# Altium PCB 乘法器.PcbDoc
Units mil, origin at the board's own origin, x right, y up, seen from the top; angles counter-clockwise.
Board outline 6000 x 4000 mil, 2 copper layers (Top Layer, Bottom Layer); 16 components, 10 nets, 49 pads, 0 vias.
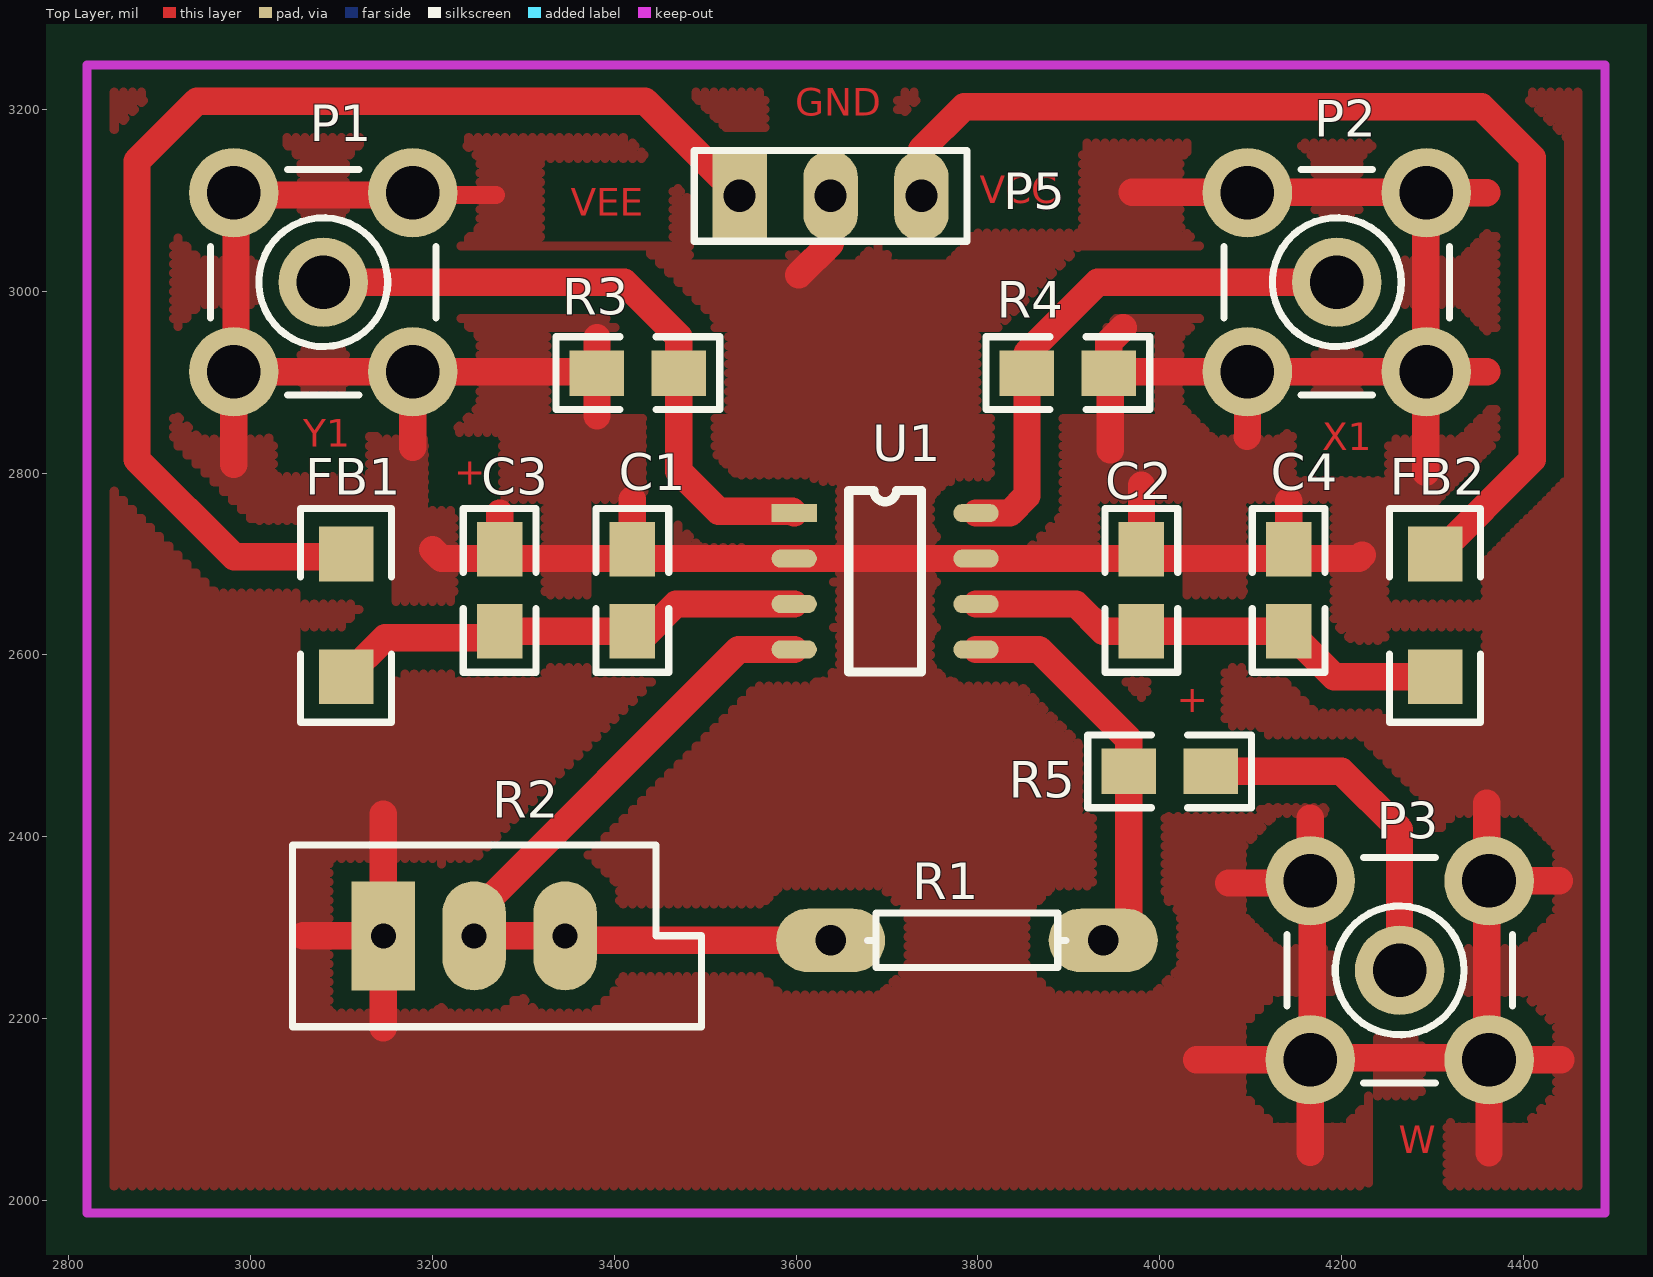
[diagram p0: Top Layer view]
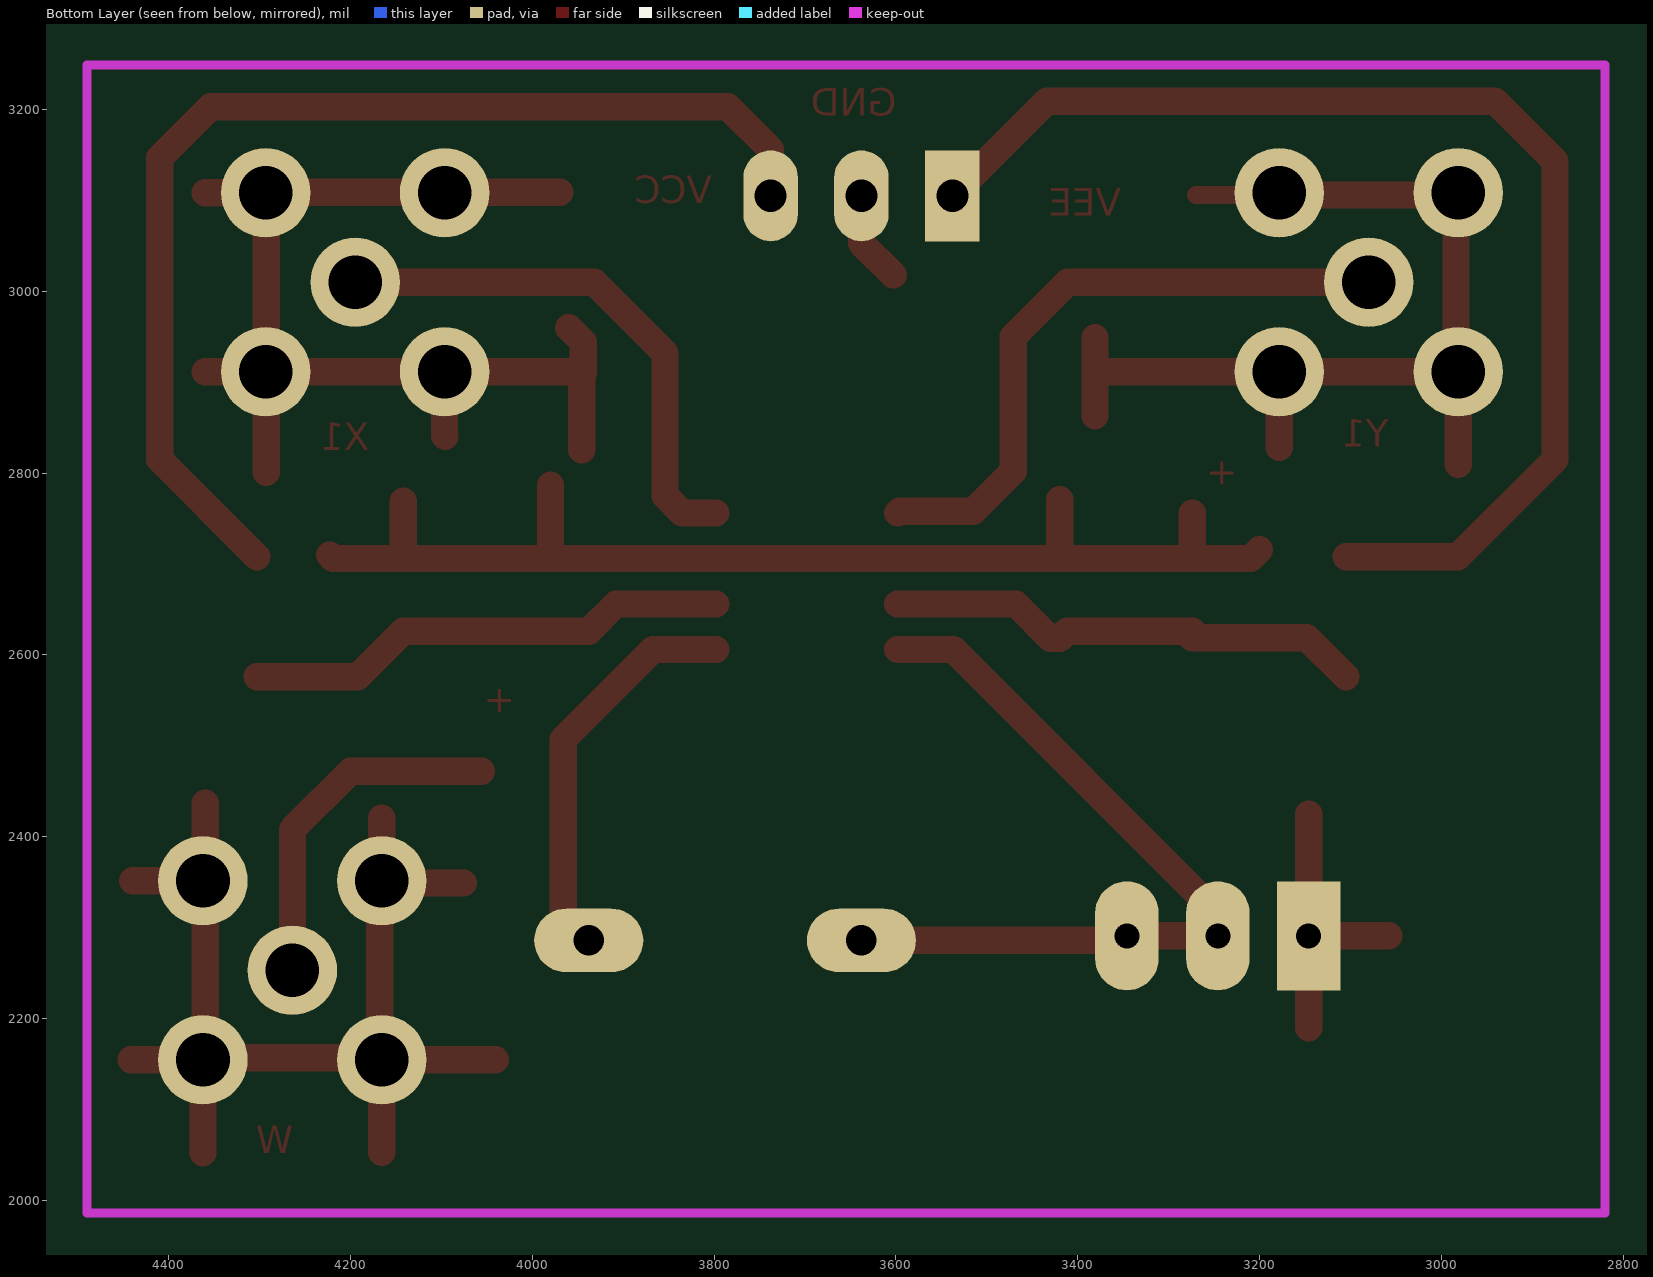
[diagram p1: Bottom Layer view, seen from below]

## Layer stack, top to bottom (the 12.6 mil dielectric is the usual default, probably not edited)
Top Layer: signal copper 1.4
Dielectric: dielectric 12.6, FR-4, Dk 4.8
Bottom Layer: signal copper 1.4

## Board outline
1000,1000 7000,1000 7000,5000 1000,5000

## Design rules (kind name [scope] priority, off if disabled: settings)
Clearance [All] p1: gap=20
PolygonConnect [All] p1: connectstyle=Relief reliefconductorwidth=10 reliefentries=4 polygonreliefangle="90 Angle"
RoutingVias [All] p1: holewidth=28 width=50 viastyle="Through Hole" minholewidth=28 minwidth=50 maxholewidth=28 maxwidth=50
SilkscreenOverComponentPads [All] p1: minsilkscreentomaskgap=10
SolderMaskExpansion [All] p1: expansion=4
Width [All] p1: maxlimit=50 minlimit=20 preferedwidth=30
27 further rules are at their usual default settings.

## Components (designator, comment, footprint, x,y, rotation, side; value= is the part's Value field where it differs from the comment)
C1 "Cap Pol3" 0805 3420,2716 r270 top
C2 "Cap Pol3" 0805 3980,2626 r90 top
C3 "Cap Semi" 0805 3274,2626 r90 top
C4 "Cap Semi" 0805 4142,2626 r90 top
FB1 "Res2" 1206 3105,2576 r90 top
FB2 "Res2" 1206 4303,2711 r270 top
P1 "SMB" SMB_V-RJ45 3080,3010 r0 top
P2 "SMB" SMB_V-RJ45 4195,3010 r0 top
P3 "SMB" SMB_V-RJ45 4264,2253 r270 top
P5 "Header 3" HDR1X3 3538,3105 r0 top
R1 "Res1" AXIAL-0.3 3788,2286 r0 top
R2 "RPot" VR5 3246,2291 r0 top
R3 "Res1" 0805 3471,2910 r180 top
R4 "Res1" 0805 3944,2910 r180 top
R5 "Res1" 0805 4056,2472 r180 top
U1 "AD835" "AD835_SOP8 - duplicate1" 3598,2756 r0 top

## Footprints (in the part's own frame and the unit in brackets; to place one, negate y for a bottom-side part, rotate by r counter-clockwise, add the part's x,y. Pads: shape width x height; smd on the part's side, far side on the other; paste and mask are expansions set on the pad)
0805 [mil]
  rect 60x50 smd: 1(0,0) 2(90,0)
  silkscreen extent -45,-40 135,40
1206 [mil]
  rect 60x60 smd: 1(0,0) 2(135,0)
  silkscreen extent -50,-50 185,50
"AD835_SOP8 - duplicate1" [mil]
  rect 50x20 smd: 1(0,0)
  oval 50x20 smd: 2(0,-50) 3(0,-100) 4(0,-150) 5(200,-150) 6(200,-100) 7(200,-50) 8(200,0)
  silkscreen extent 60,-175 140,25
AXIAL-0.3 [mil] "Axial Device, Thru-Hole; 2 Leads; 0.3 in P"
  oval 120x70 hole 33.46: 1(-150,0) 2(150,0)
  silkscreen extent -109,-30 109,30
HDR1X3 [mil] "Connector; Header;"
  rect 60x100 hole 35.43: 1(0,0)
  oval 60x100 hole 35.43: 2(100,0) 3(200,0)
  silkscreen extent -50,-50 250,50
SMB_V-RJ45 [mm] "Connector; S"
  round 2.5 hole 1.5: 1(0,0) 2(-2.5,-2.5) 2(-2.5,2.5) 2(2.5,-2.5) 2(2.5,2.5)
  silkscreen extent -3.15,-3.15 3.15,3.15
VR5 [mil] "Thru-Hol"
  rect 70x120 hole 27.56: 1(-100,0)
  oval 70x120 hole 27.56: 2(0,0) 3(100,0)
  silkscreen extent -200,-100 250,100

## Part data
C1 C2: "Polarized Capacitor"
C3 C4: "Capacitor (Semicond"
P1 P2 P3: "SMB Straight Connector"
P5: "Header, 3-Pin"
R1: "Resistor"
R2: "Potentiometer"
U1: library part Compone

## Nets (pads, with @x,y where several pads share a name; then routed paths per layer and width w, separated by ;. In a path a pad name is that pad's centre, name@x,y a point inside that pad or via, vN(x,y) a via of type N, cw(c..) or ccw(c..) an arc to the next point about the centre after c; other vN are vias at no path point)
GND: C1.1 C2.2 C3.2 C4.2 P1.2 P2.2 P3.2 P5.2 R2.1 R3.2 R4.1 U1.2 U1.7 | length 5461.2
  Top Layer w20: P1.2@3180.85,3106 3270,3106
  Top Layer w30: 2981.57,2809.57 2981.57,2911.57 P1.2@2984,2911.57 ; 3058,2291 R2.1 ; 3146,2190 R2.1 ; 3146,2425 R2.1 ; 3178.43,2828.43 P1.2@3178.43,2911.57 ; P1.2@3180.85,3106 2984,3106 P1.2@2984,2911.57 ; 3200,2716 3210,2706 U1.2 U1.7 4219,2706 4223,2710 ; C3.2 3274,2756 ; 3381,2863 R3.2 ; 3381,2949 R3.2 ; C1.1 3420,2771 ; 3603,3018 3638,3053 P5.2 ; R4.1 3944,2944 3960,2960 ; 3945.57,2825.43 3945.57,2911.57 P2.2@4096.57,2911.57 ; 3970,3109 4292.85,3109 P2.2@4292.85,2911.57 ; C2.2 3980,2787 ; 4040.57,2154.57 4165.57,2154.57 4165.57,2052.57 ; 4076,2349 4168,2349 4168,2157 4360,2157 4360,2437 ; 4096,2840.21 4096.57,2840.79 P2.2@4096.57,2911.57 ; C4.2 4142,2769 ; P3.2@4165.57,2351.43 4165.57,2420.64 ; 4292.85,2800.85 P2.2@4292.85,2911.57 ; P2.2@4293.43,3108.43 4360,3108.43 ; 4360,2911.57 4293.43,2911.57 P2.2@4292.85,2911.57 ; 4362.43,2052.43 4362.43,2154.57 4441.57,2154.57 ; P3.2@4362.43,2351.43 4439.75,2351.43 ; P1.2@2984,2911.57 P1.2@3178.43,2911.57 ; P1.2@3178.43,2911.57 3379.43,2911.57 R3.2 ; P2.2@4096.57,2911.57 P2.2@4292.85,2911.57
NetC1_2: C1.2 C3.1 FB1.1 U1.3 | length 529.9
  Top Layer w30: FB1.1 3148,2619 C3.1@3274,2619 ; C3.1 3412,2626 3420,2618 3430,2618 3468,2656 U1.3
NetC2_1: C2.1 C4.1 FB2.2 U1.6 | length 538.1
  Top Layer w30: U1.6 3908,2656 3938,2626 C2.1 C4.1 4192,2576 FB2.2
NetR1_1: R1.1 R2.2 R2.3 U1.4 | length 890.6
  Top Layer w30: U1.4 3537,2606 3246,2315 R2.2 R2.3 3351,2286 R1.1
NetR1_2: R1.2 R5.2 U1.5 | length 441.6
  Top Layer w30: U1.5 3867,2606 3966,2507 R5.2 3966,2314 R1.2
VCC: FB2.1 P5.3 | length 1249
  Top Layer w30: P5.3 3738,3156 3785,3203 4354,3203 4410,3147 4410,2815 FB2.1@4303,2708
VEE: FB1.2 P5.1 | length 1335.7
  Top Layer w30: FB1.2@3105,2708 2982,2708 2875,2815 2875,3143 2941,3209 3434,3209 P5.1
W: P3.1 R5.1 | length 389.5
  Top Layer w30: R5.1 4200,2472 4264,2408 P3.1
X1: P2.1 R4.2 U1.8 | length 594.2
  Top Layer w30: U1.8 3835,2756 3854,2775 3854,2914 3854,2932 3932,3010 P2.1
Y1: P1.1 R3.1 U1.1 | length 709.9
  Top Layer w30: P1.1 3411,3010 3471,2950 R3.1 3471,2802 3515,2758 3596,2758 U1.1

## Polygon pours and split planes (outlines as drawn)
GND on Top Layer "Bottom Layer-No Net" (hatched 90Degree grid 10 track 10, pour order 15): 2820,3249 4484,3249 4490,3243 4490,1986 2827,1986 2818,1995

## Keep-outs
Keep-Out Layer:
  lines w10: 2820,1986 4490,1986 4490,3249 2820,3249 2820,1986

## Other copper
Top Layer:
  text "GND" at 3599,3193 h30
  text "VCC" at 3802,3097 h30
  text "VEE" at 3352,3083 h30
  text "Y1" at 3058,2829 h30
  text "X1" at 4179,2825 h30
  text "+" at 3224,2787 h30
  text "+" at 4019,2537 h30
  text "W" at 4263,2052 h30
